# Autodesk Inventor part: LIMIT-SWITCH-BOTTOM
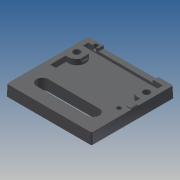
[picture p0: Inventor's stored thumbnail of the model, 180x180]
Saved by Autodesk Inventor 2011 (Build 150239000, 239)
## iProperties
Created: 2010-08
Part Number: LIMIT-SWITCH-BOTTOM
Material: ABS Plastic
Document SubType Name: Modeling
Density: 1.06 g/cm^3
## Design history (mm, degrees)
feature "Base1"
workplane "Work Plane1"
body "Solid1"
